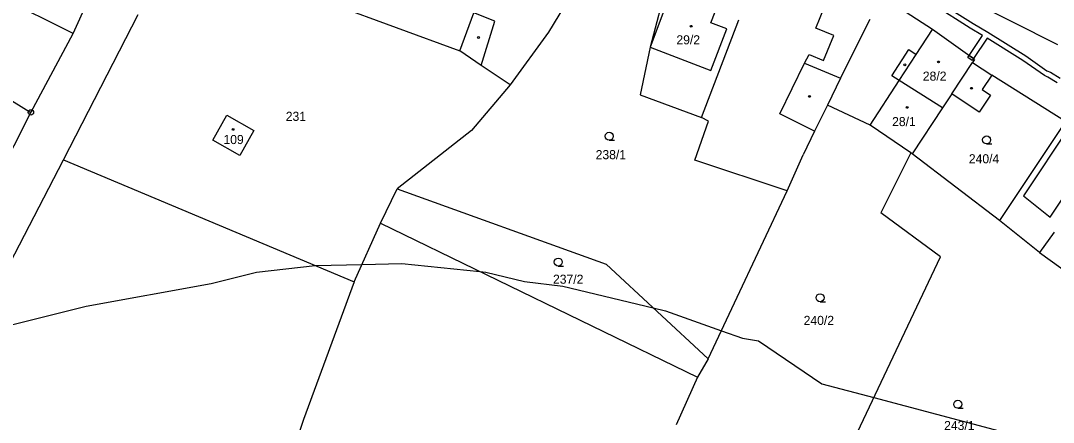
# Model space of a CAD drawing. Extents: x -747333 to -745433, y -1133152 to -1130600.
# Drawn here: x -746635.6 to -746442.1, y -1132218.2 to -1132143.1 of the extents above; entities that cross this region are included whole.
import ezdxf

# ---------------------------------------------------------------- set-up
doc = ezdxf.new("R2010")
doc.units = 0
for name, color, linetype in [('Vrstva 1', 7, 'Continuous'), ('Vrstva 18', 7, 'Continuous'), ('Vrstva 19', 7, 'Continuous'), ('Vrstva 24', 7, 'Continuous'), ('Vrstva 25', 7, 'Continuous'), ('Vrstva 3', 7, 'Continuous'), ('Vrstva 30', 7, 'Continuous'), ('Vrstva 37', 7, 'Continuous'), ('Vrstva 4', 7, 'Continuous'), ('Vrstva 52', 7, 'Continuous')]:
    doc.layers.add(name, color=color, linetype=linetype)

msp = doc.modelspace()

# ---------------------------------------------------------------- linework, layer by layer
at = {"layer": 'Vrstva 1'}
for p, q in [((-746625.72, -1132145.44), (-746659.43, -1132128.69)), ((-746633.63, -1132160.23), (-746625.72, -1132145.44)), ((-746653.23, -1132148.18), (-746633.63, -1132160.23)), ((-746643.87, -1132180.43), (-746633.63, -1132160.23))]:
    msp.add_line(p, q, dxfattribs=at)
for points in [[(-746526.85, -1132128.93), (-746536.7, -1132145.21)], [(-746625.72, -1132145.44), (-746620.55, -1132133.99)], [(-746514.46, -1132135.87), (-746517.68, -1132148.02)], [(-746577.16, -1132139.99), (-746553.33, -1132148.74)], [(-746464.75, -1132144.73), (-746474.8, -1132138.2)], [(-746458.58, -1132138.82), (-746441.38, -1132147.52)], [(-746627.53, -1132169.14), (-746613.53, -1132141.89)], [(-746486.65, -1132144.48), (-746485, -1132140.49)], [(-746508.03, -1132161.18), (-746501.07, -1132142.89)], [(-746476.52, -1132142.87), (-746478.77, -1132147.26)], [(-746536.7, -1132145.21), (-746543.9, -1132155.07)], [(-746483.26, -1132145.87), (-746486.65, -1132144.48)], [(-746467.81, -1132149.4), (-746464.75, -1132144.73)], [(-746456.89, -1132150.33), (-746464.75, -1132144.73)], [(-746485.17, -1132150.55), (-746483.26, -1132145.87)], [(-746478.77, -1132147.26), (-746481.98, -1132153.82)], [(-746549.28, -1132151.46), (-746553.33, -1132148.74)], [(-746517.68, -1132148.02), (-746519.55, -1132156.97)], [(-746488.73, -1132150.99), (-746487.86, -1132149.42)], [(-746487.86, -1132149.42), (-746485.17, -1132150.55)], [(-746471.01, -1132154.29), (-746467.81, -1132149.4)], [(-746543.9, -1132155.07), (-746549.28, -1132151.46)], [(-746488.73, -1132150.99), (-746481.98, -1132153.82)], [(-746456.89, -1132150.33), (-746457.28, -1132150.91)], [(-746457.28, -1132150.91), (-746453.69, -1132153.29)], [(-746453.69, -1132153.29), (-746455.46, -1132155.96)], [(-746439.9, -1132161.92), (-746453.69, -1132153.29)], [(-746543.9, -1132155.07), (-746551.09, -1132163.59)], [(-746481.98, -1132153.82), (-746484.47, -1132158.9)], [(-746462.92, -1132159.41), (-746471.01, -1132154.29)], [(-746519.55, -1132156.97), (-746508.03, -1132161.18)], [(-746461.18, -1132156.79), (-746462.92, -1132159.41)], [(-746456.05, -1132160.19), (-746461.18, -1132156.79)], [(-746453.92, -1132156.98), (-746456.05, -1132160.19)], [(-746455.46, -1132155.96), (-746453.92, -1132156.98)], [(-746484.47, -1132158.9), (-746486.86, -1132163.77)], [(-746476.47, -1132162.64), (-746484.47, -1132158.9)], [(-746599.53, -1132165.41), (-746596.96, -1132160.78)], [(-746596.96, -1132160.78), (-746591.89, -1132163.64)], [(-746506.73, -1132161.88), (-746508.03, -1132161.18)], [(-746462.92, -1132159.41), (-746468.6, -1132167.97)], [(-746509.28, -1132169.18), (-746506.73, -1132161.88)], [(-746468.85, -1132167.8), (-746476.47, -1132162.64)], [(-746439.9, -1132161.92), (-746452.21, -1132180.46)], [(-746591.89, -1132163.64), (-746594.5, -1132168.32)], [(-746551.09, -1132163.59), (-746565.04, -1132174.52)], [(-746486.86, -1132163.77), (-746489.02, -1132168.19)], [(-746594.5, -1132168.32), (-746599.53, -1132165.41)], [(-746492.01, -1132174.94), (-746489.02, -1132168.19)], [(-746468.85, -1132167.8), (-746474.43, -1132179.05)], [(-746468.6, -1132167.97), (-746468.85, -1132167.8)], [(-746452.21, -1132180.46), (-746468.6, -1132167.97)], [(-746637.59, -1132188.53), (-746627.53, -1132169.14)], [(-746627.53, -1132169.14), (-746573.08, -1132191.94)], [(-746492.01, -1132174.94), (-746509.28, -1132169.18)], [(-746568.17, -1132180.98), (-746565.04, -1132174.52)], [(-746565.04, -1132174.52), (-746525.9, -1132188.66)], [(-746506.79, -1132206.34), (-746492.01, -1132174.94)], [(-746463.28, -1132187.24), (-746474.43, -1132179.05)], [(-746444.75, -1132186.48), (-746452.21, -1132180.46)], [(-746573.08, -1132191.94), (-746568.17, -1132180.98)], [(-746568.17, -1132180.98), (-746508.81, -1132209.8)], [(-746441.98, -1132182.67), (-746444.75, -1132186.48)], [(-746488.24, -1132239.95), (-746463.28, -1132187.24)], [(-746444.75, -1132186.48), (-746430.73, -1132196.48)], [(-746525.9, -1132188.66), (-746506.79, -1132206.34)], [(-746573.08, -1132191.94), (-746582.55, -1132217.69)], [(-746506.79, -1132206.34), (-746508.81, -1132209.8)], [(-746508.81, -1132209.8), (-746512.76, -1132218.71)], [(-746582.55, -1132217.69), (-746594.73, -1132254.38)]]:
    msp.add_lwpolyline(points, dxfattribs=at)
at = {"layer": 'Vrstva 24'}
msp.add_line((-746633.68, -1132160.23), (-746633.58, -1132160.23), dxfattribs=at)
msp.add_circle((-746633.63, -1132160.23), 0.499289, dxfattribs=at)
at = {"layer": 'Vrstva 25'}
for p, q in [((-746525.33, -1132165.44), (-746524.33, -1132165.44)), ((-746454.65, -1132166.12), (-746453.65, -1132166.12)), ((-746534.87, -1132188.99), (-746533.87, -1132188.99)), ((-746485.84, -1132195.67), (-746484.84, -1132195.67)), ((-746460.04, -1132215.6), (-746459.04, -1132215.6))]:
    msp.add_line(p, q, dxfattribs=at)
for centre, radius in [((-746509.97, -1132144.12), 0.174503), ((-746549.79, -1132146.23), 0.174503), ((-746469.95, -1132151.33), 0.174503), ((-746463.65, -1132150.79), 0.174503), ((-746487.82, -1132157.23), 0.174503), ((-746457.49, -1132155.72), 0.174503), ((-746469.53, -1132159.29), 0.174503), ((-746595.77, -1132163.41), 0.174503), ((-746525.33, -1132164.69), 0.75), ((-746454.65, -1132165.37), 0.75), ((-746534.87, -1132188.24), 0.75), ((-746485.84, -1132194.92), 0.75), ((-746460.04, -1132214.85), 0.75)]:
    msp.add_circle(centre, radius, dxfattribs=at)
at = {"layer": 'Vrstva 3'}
for points in [[(-746514.71, -1132140.21), (-746517.68, -1132148.02)], [(-746506.31, -1132143.45), (-746505.51, -1132141.4)], [(-746503.27, -1132144.62), (-746506.31, -1132143.45)], [(-746506.28, -1132152.42), (-746503.27, -1132144.62)], [(-746467.81, -1132149.4), (-746464.75, -1132144.73)], [(-746456.89, -1132150.33), (-746464.75, -1132144.73)], [(-746517.68, -1132148.02), (-746506.28, -1132152.42)], [(-746471.01, -1132154.29), (-746467.81, -1132149.4)], [(-746461.18, -1132156.79), (-746457.28, -1132150.91)], [(-746456.89, -1132150.33), (-746457.28, -1132150.91)], [(-746476.47, -1132162.64), (-746471.01, -1132154.29)], [(-746462.92, -1132159.41), (-746471.01, -1132154.29)], [(-746462.92, -1132159.41), (-746471.01, -1132154.29)], [(-746461.18, -1132156.79), (-746462.92, -1132159.41)], [(-746599.53, -1132165.41), (-746596.96, -1132160.78)], [(-746596.96, -1132160.78), (-746591.89, -1132163.64)], [(-746462.92, -1132159.41), (-746468.6, -1132167.97)], [(-746468.85, -1132167.8), (-746476.47, -1132162.64)], [(-746591.89, -1132163.64), (-746594.5, -1132168.32)], [(-746594.5, -1132168.32), (-746599.53, -1132165.41)], [(-746468.6, -1132167.97), (-746468.85, -1132167.8)]]:
    msp.add_lwpolyline(points, dxfattribs=at)
at = {"layer": 'Vrstva 30'}
for points in [[(-746463.87, -1132139.39), (-746457.18, -1132143.62)], [(-746457.7, -1132144.48), (-746464.41, -1132140.23)], [(-746457.18, -1132143.62), (-746454.41, -1132145.23)], [(-746457.94, -1132149.58), (-746455.39, -1132145.82)], [(-746455.39, -1132145.82), (-746457.7, -1132144.48)], [(-746454.41, -1132145.23), (-746447.32, -1132149.67)], [(-746454.53, -1132146.34), (-746457.13, -1132150.16)], [(-746447.88, -1132150.51), (-746454.53, -1132146.34)], [(-746458.19, -1132149.93), (-746457.94, -1132149.58)], [(-746457.13, -1132150.16), (-746457.94, -1132149.58)], [(-746457.94, -1132149.58), (-746457.13, -1132150.16)], [(-746447.32, -1132149.67), (-746443.35, -1132152.43)], [(-746457.36, -1132150.5), (-746458.19, -1132149.93)], [(-746457.13, -1132150.16), (-746457.36, -1132150.5)], [(-746443.83, -1132153.31), (-746447.88, -1132150.51)], [(-746443.15, -1132153.61), (-746443.83, -1132153.31)], [(-746443.35, -1132152.43), (-746442.67, -1132152.73)], [(-746442.67, -1132152.73), (-746440.86, -1132153.85)], [(-746441.41, -1132154.69), (-746443.15, -1132153.61)]]:
    msp.add_lwpolyline(points, dxfattribs=at)
at = {"layer": 'Vrstva 37'}
for centre in [(-746509.97, -1132144.12), (-746463.65, -1132150.79), (-746469.53, -1132159.29), (-746595.77, -1132163.41)]:
    msp.add_circle(centre, 0.174503, dxfattribs=at)
at = {"layer": 'Vrstva 4'}
for points in [[(-746553.33, -1132148.74), (-746550.66, -1132141.62)], [(-746546.74, -1132143.19), (-746550.66, -1132141.62)], [(-746514.71, -1132140.21), (-746517.68, -1132148.02)], [(-746506.31, -1132143.45), (-746505.51, -1132141.4)], [(-746549.28, -1132151.46), (-746546.74, -1132143.19)], [(-746503.27, -1132144.62), (-746506.31, -1132143.45)], [(-746506.28, -1132152.42), (-746503.27, -1132144.62)], [(-746517.68, -1132148.02), (-746506.28, -1132152.42)], [(-746472.4, -1132153.39), (-746469.22, -1132148.47)], [(-746469.22, -1132148.47), (-746467.81, -1132149.4)], [(-746493.39, -1132160.49), (-746488.73, -1132150.99)], [(-746461.18, -1132156.79), (-746457.28, -1132150.91)], [(-746471.01, -1132154.29), (-746472.4, -1132153.39)], [(-746476.47, -1132162.64), (-746471.01, -1132154.29)], [(-746486.86, -1132163.77), (-746493.39, -1132160.49)], [(-746438.91, -1132162.6), (-746447.75, -1132175.82)], [(-746442.73, -1132179.87), (-746433.6, -1132166.24)], [(-746447.75, -1132175.82), (-746442.73, -1132179.87)]]:
    msp.add_lwpolyline(points, dxfattribs=at)
at = {"layer": 'Vrstva 52'}
msp.add_lwpolyline([(-746645.81, -1132202.12), (-746623.31, -1132196.5), (-746599.87, -1132192.25), (-746591.37, -1132190.12), (-746580.38, -1132188.88), (-746580.31, -1132188.88), (-746571.62, -1132188.67), (-746564.19, -1132188.5), (-746549.58, -1132190.01), (-746548.44, -1132190.12), (-746541.19, -1132191.88), (-746534, -1132192.75), (-746517.07, -1132196.83), (-746514.81, -1132197.37), (-746504.32, -1132201.1), (-746500.38, -1132202.5), (-746497.38, -1132203), (-746485.5, -1132211), (-746475.76, -1132213.59), (-746445.5, -1132221.62)], dxfattribs=at)

# ---------------------------------------------------------------- texts
at = {"layer": 'Vrstva 18'}
for s, p in [('231', (-746585.9, -1132161.82)), ('238/1', (-746527.86, -1132168.99)), ('240/4', (-746457.97, -1132169.76)), ('237/2', (-746535.85, -1132192.3)), ('240/2', (-746488.91, -1132200.01)), ('243/1', (-746462.6, -1132219.68))]:
    msp.add_text(s, height=1.7, dxfattribs=at).set_placement(p)
at = {"layer": 'Vrstva 19'}
for s, p in [('29/2', (-746512.74, -1132147.5)), ('28/2', (-746466.59, -1132154.3)), ('28/1', (-746472.34, -1132162.8)), ('109', (-746597.57, -1132166.16))]:
    msp.add_text(s, height=1.7, dxfattribs=at).set_placement(p)

doc.saveas('drawing.dxf')
